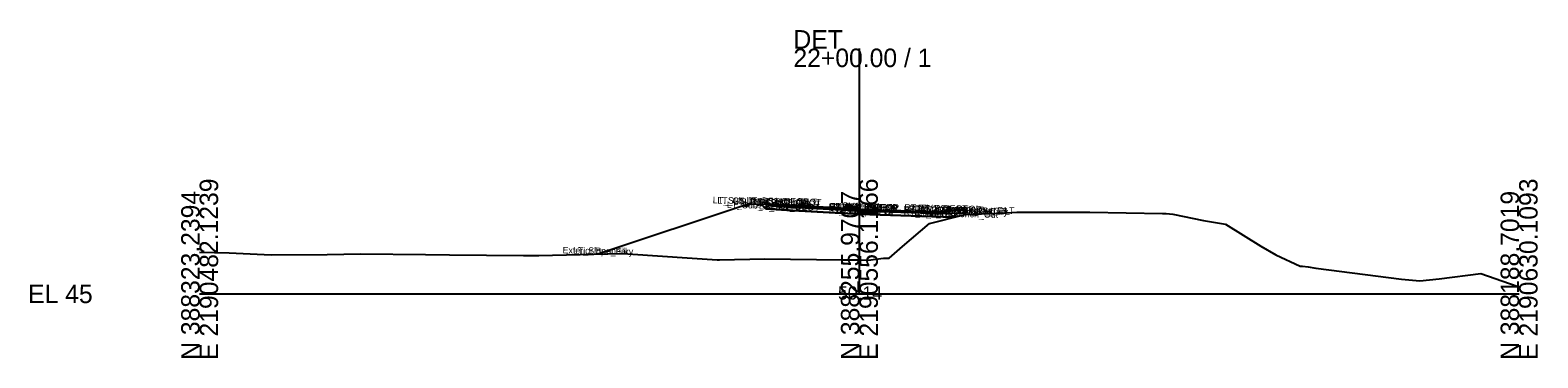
# Model space of a CAD drawing. Extents: x -26 to 1203, y -10 to 9543.
# Drawn here: x 974.3 to 1202.8, y 1990.3 to 2040 of the extents above; entities that cross this region are included whole.
import ezdxf

# ---------------------------------------------------------------- set-up
doc = ezdxf.new("R2010")
doc.units = 0
for name, color, linetype in [('Default', 7, 'Continuous'), ('Exist Cross Section Cell', 7, 'Continuous'), ('Exist XS Center Line Elevation Label', 7, 'Continuous'), ('Exist XS Ground Line', 7, 'Continuous'), ('Prop CMT Pvmt Course 1', 7, 'Continuous'), ('Prop CMT Pvmt Course 2', 7, 'Continuous'), ('Prop CMT Pvmt Course 3', 7, 'Continuous'), ('Prop CMT Pvmt Surface', 7, 'Continuous'), ('Prop CMT Pvmt Surface Shoulder', 7, 'Continuous'), ('Prop CMT Shld Paved Course 1', 7, 'Continuous'), ('Prop CMT Shld Paved Course 2', 7, 'Continuous'), ('Prop CMT Shld Paved Course 3', 7, 'Continuous'), ('Prop CMT Slope Grass', 7, 'Continuous'), ('Prop CMT Subgrade Earthwork', 7, 'Continuous'), ('Scratch_Level_0', 7, 'Continuous')]:
    doc.layers.add(name, color=color, linetype=linetype)

msp = doc.modelspace()

# ---------------------------------------------------------------- linework, layer by layer
at = {"layer": 'Exist Cross Section Cell'}
for p, q in [((1100, 2000), (1100, 2037.17)), ((1000, 2000), (1100, 2000)), ((1100, 2000), (1200, 2000))]:
    msp.add_line(p, q, dxfattribs=at)
at = {"layer": 'Exist XS Ground Line'}
for p, q in [((1110.64, 2010.66), (1115.65, 2011.93)), ((1115.65, 2011.93), (1115.98, 2012.02)), ((1115.98, 2012.02), (1122.28, 2012.28)), ((1122.28, 2012.28), (1123.08, 2012.32)), ((1123.08, 2012.32), (1123.86, 2012.38)), ((1123.86, 2012.38), (1131.6, 2012.39)), ((1131.6, 2012.39), (1134.93, 2012.39)), ((1134.93, 2012.39), (1140.43, 2012.3)), ((1140.43, 2012.3), (1145.95, 2012.2)), ((1145.95, 2012.2), (1146.5, 2012.16)), ((1146.5, 2012.16), (1147.49, 2012.1)), ((1147.49, 2012.1), (1152.17, 2011.14)), ((1152.17, 2011.14), (1155.51, 2010.56)), ((1106.53, 2007.17), (1110.64, 2010.66)), ((1155.51, 2010.56), (1160.86, 2007.23)), ((1104.5, 2005.39), (1106.53, 2007.17)), ((1160.86, 2007.23), (1163.14, 2005.92)), ((1000, 2006.33), (1004.47, 2006.2)), ((1004.47, 2006.2), (1010.85, 2005.9)), ((1010.85, 2005.9), (1019.34, 2005.99)), ((1019.34, 2005.99), (1024.37, 2006.08)), ((1024.37, 2006.08), (1034.21, 2005.97)), ((1034.21, 2005.97), (1037.88, 2005.93)), ((1037.88, 2005.93), (1049.08, 2005.82)), ((1049.08, 2005.82), (1050.29, 2005.82)), ((1050.29, 2005.82), (1051.4, 2005.83)), ((1051.4, 2005.83), (1063.94, 2006.1)), ((1063.94, 2006.1), (1064.92, 2006.09)), ((1064.92, 2006.09), (1074.67, 2005.41)), ((1074.67, 2005.41), (1078.43, 2005.16)), ((1078.43, 2005.16), (1078.81, 2005.14)), ((1078.81, 2005.14), (1085.69, 2005.31)), ((1085.69, 2005.31), (1097.38, 2005.17)), ((1097.38, 2005.17), (1100, 2005.14)), ((1100, 2005.14), (1101.31, 2005.13)), ((1101.31, 2005.13), (1103.68, 2005.39)), ((1103.68, 2005.39), (1104.5, 2005.39)), ((1163.14, 2005.92), (1166.8, 2004.22)), ((1166.8, 2004.22), (1167.15, 2004.18)), ((1167.15, 2004.18), (1168.03, 2004.08)), ((1168.03, 2004.08), (1169.19, 2003.91)), ((1169.19, 2003.91), (1182.19, 2002.22)), ((1182.19, 2002.22), (1184.93, 2001.98)), ((1184.93, 2001.98), (1187.87, 2002.29)), ((1187.87, 2002.29), (1194.21, 2003.11)), ((1194.21, 2003.11), (1198.55, 2001.56)), ((1198.55, 2001.56), (1200, 2001.08))]:
    msp.add_line(p, q, dxfattribs=at)
at = {"layer": 'Prop CMT Pvmt Course 1'}
for points in [[(1100, 2012.83), (1089, 2013.46)], [(1089, 2013.46), (1089, 2013.21)], [(1089, 2013.21), (1100, 2012.58)], [(1100, 2012.58), (1100, 2012.83)], [(1100, 2012.83), (1111, 2012.5)], [(1100, 2012.58), (1100, 2012.83)], [(1111, 2012.25), (1100, 2012.58)], [(1111, 2012.5), (1111, 2012.25)]]:
    msp.add_lwpolyline(points, dxfattribs=at)
msp.add_lwpolyline([(1100, 2012.58), (1100, 2012.7), (1100, 2012.7), (1100, 2012.58)], close=True, dxfattribs=at)
msp.add_lwpolyline([(1100, 2012.58), (1100, 2012.7), (1100, 2012.7), (1100, 2012.58)], close=True, dxfattribs=at)
at = {"layer": 'Prop CMT Pvmt Course 2'}
for points in [[(1089, 2013.21), (1100, 2012.58)], [(1100, 2012.58), (1089, 2013.21)], [(1089, 2013.21), (1089, 2013.21)], [(1100, 2012.58), (1100, 2012.58)], [(1111, 2012.25), (1100, 2012.58)], [(1100, 2012.58), (1100, 2012.58)], [(1100, 2012.58), (1111, 2012.25)], [(1111, 2012.25), (1111, 2012.25)]]:
    msp.add_lwpolyline(points, dxfattribs=at)
at = {"layer": 'Prop CMT Pvmt Course 3'}
for points in [[(1100, 2012.58), (1089, 2013.21)], [(1089, 2013.21), (1089, 2012.71)], [(1089, 2012.71), (1100, 2012.08)], [(1100, 2012.08), (1100, 2012.58)], [(1100, 2012.58), (1111, 2012.25)], [(1100, 2012.08), (1100, 2012.58)], [(1111, 2011.75), (1100, 2012.08)], [(1111, 2012.25), (1111, 2011.75)]]:
    msp.add_lwpolyline(points, dxfattribs=at)
at = {"layer": 'Prop CMT Pvmt Surface'}
for points in [[(1100, 2012.83), (1089, 2013.46)], [(1100, 2012.83), (1111, 2012.5)]]:
    msp.add_lwpolyline(points, dxfattribs=at)
at = {"layer": 'Prop CMT Pvmt Surface Shoulder'}
for points in [[(1089, 2013.46), (1087, 2013.58)], [(1111, 2012.5), (1113, 2012.44)]]:
    msp.add_lwpolyline(points, dxfattribs=at)
at = {"layer": 'Prop CMT Shld Paved Course 1'}
for points in [[(1089, 2013.46), (1087, 2013.58), (1086.76, 2013.34)], [(1089, 2013.21), (1089, 2013.46)], [(1086.76, 2013.34), (1089, 2013.21)], [(1111, 2012.5), (1113, 2012.44), (1113.26, 2012.18)], [(1111, 2012.25), (1111, 2012.5)], [(1113.26, 2012.18), (1111, 2012.25)]]:
    msp.add_lwpolyline(points, dxfattribs=at)
at = {"layer": 'Prop CMT Shld Paved Course 2'}
for points in [[(1089, 2013.21), (1086.76, 2013.34)], [(1086.76, 2013.34), (1086.76, 2013.34)], [(1086.76, 2013.34), (1089, 2013.21)], [(1089, 2013.21), (1089, 2013.21)], [(1111, 2012.25), (1113.26, 2012.18)], [(1113.26, 2012.18), (1111, 2012.25)], [(1111, 2012.25), (1111, 2012.25)], [(1113.26, 2012.18), (1113.26, 2012.18)]]:
    msp.add_lwpolyline(points, dxfattribs=at)
at = {"layer": 'Prop CMT Shld Paved Course 3'}
for points in [[(1089, 2013.21), (1086.76, 2013.34), (1086.26, 2013.37), (1085.79, 2012.9)], [(1085.79, 2012.9), (1089, 2012.71)], [(1089, 2012.71), (1089, 2013.21)], [(1111, 2012.25), (1113.26, 2012.18), (1113.76, 2012.16), (1114.27, 2011.65)], [(1111, 2011.75), (1111, 2012.25)], [(1114.27, 2011.65), (1111, 2011.75)]]:
    msp.add_lwpolyline(points, dxfattribs=at)
at = {"layer": 'Prop CMT Slope Grass'}
msp.add_lwpolyline([(1087, 2013.58), (1083, 2013.57), (1060.35, 2006.02)], dxfattribs=at)
at = {"layer": 'Prop CMT Subgrade Earthwork'}
for points in [[(1085.79, 2012.9), (1085.11, 2013.58)], [(1089, 2012.71), (1085.79, 2012.9)], [(1100, 2012.08), (1089, 2012.71)], [(1100, 2012.08), (1111, 2011.75)], [(1111, 2011.75), (1114.27, 2011.65)], [(1114.27, 2011.65), (1114.91, 2012.28)]]:
    msp.add_lwpolyline(points, dxfattribs=at)

# ---------------------------------------------------------------- texts
at = {"layer": 'Default'}
msp.add_text('-', height=0.0001, dxfattribs=at).set_placement((1000, 2000))
at = {"layer": 'Exist Cross Section Cell'}
for s, p in [('DET', (1090, 2037.17)), ('22+00.00 / 1', (1090, 2034.37)), ('EL 45', (974, 1998.6))]:
    msp.add_text(s, height=2.8, dxfattribs=at).set_placement(p)
for s, p in [('E 2190482.1239', (1002.8, 1990)), ('E 2190556.1166', (1102.8, 1990)), ('E 2190630.1093', (1202.8, 1990)), ('N 388323.2394', (1000, 1990)), ('N 388255.9707', (1100, 1990)), ('N 388188.7019', (1200, 1990))]:
    msp.add_text(s, height=2.8, rotation=90, dxfattribs=at).set_placement(p)
at = {"layer": 'Exist XS Center Line Elevation Label'}
msp.add_text('50.14', height=2, dxfattribs=at).set_placement((1096.75, 1999.14))
at = {"layer": 'Scratch_Level_0'}
for s, p in [('LT_Sub_Trench_Out_DLT', (1077.77, 2013.72)), ('LT_GS_OS_CTL', (1078.46, 2013.66)), ('LT_Sub_Trench_Out', (1079.9, 2013.02)), ('LT_PS3_Shelf_Out', (1080.92, 2013.48)), ('LT_PS3_OEOP', (1082.55, 2013.43)), ('LT_PS2_OEOP', (1082.55, 2013.43)), ('LT_PS1_OEOP', (1082.91, 2013.66)), ('LT_PV2_OEOT', (1084.75, 2013.3)), ('LT_PV3_OEOT', (1084.75, 2013.3)), ('LT_Sub_OEOT', (1084.77, 2012.8)), ('LT_PV1_OEOT', (1084.87, 2013.55)), ('RT_PV2_OEEOP', (1095.33, 2012.67)), ('RT_PV3_OEEOP', (1095.33, 2012.67)), ('LT_PV2_OEEOP', (1095.39, 2012.67)), ('LT_PV3_OEEOP', (1095.39, 2012.67)), ('RT_PV1_OEEOP', (1095.45, 2012.79)), ('LT_PV1_OEEOP', (1095.51, 2012.79)), ('RT_PV2_IEEOP', (1095.71, 2012.66)), ('LT_PV2_IEEOP', (1095.77, 2012.66)), ('RT_PV1_IEEOP', (1095.83, 2012.78)), ('LT_PV1_IEEOP', (1095.89, 2012.78)), ('PV2_PGL', (1097.35, 2012.63)), ('PV1_PGL', (1097.47, 2012.87)), ('RT_PV1_OEOT', (1106.81, 2012.58)), ('RT_Sub_Trench_Out_DLT', (1107.5, 2012.43)), ('RT_PS1_OEOP', (1108.85, 2012.52)), ('RT_Sub_OEEOP', (1095.36, 2012.17)), ('LT_Sub_OEEOP', (1095.42, 2012.16)), ('RT_PV3_OEOT', (1106.69, 2012.33)), ('RT_PV2_OEOT', (1106.69, 2012.33)), ('RT_Sub_OEOT', (1106.71, 2011.83)), ('RT_Sub_Trench_Out', (1108.32, 2011.76)), ('RT_PS3_Shelf_Out', (1108.36, 2012.27)), ('RT_PS3_OEOP', (1108.99, 2012.26)), ('RT_PS2_OEOP', (1108.99, 2012.26)), ('Exterior Boundary', (1111.81, 2012.17)), ('RT_GS_OS_CTL', (1112.41, 2012.21)), ('RT_Slope_Cut', (1113.09, 2012.15)), ('Exterior Boundary', (1055.01, 2006.13)), ('LT_Slope_Fill', (1056.59, 2006.1))]:
    msp.add_text(s, height=1, rotation=358.8836, dxfattribs=at).set_placement(p)

doc.saveas('drawing.dxf')
